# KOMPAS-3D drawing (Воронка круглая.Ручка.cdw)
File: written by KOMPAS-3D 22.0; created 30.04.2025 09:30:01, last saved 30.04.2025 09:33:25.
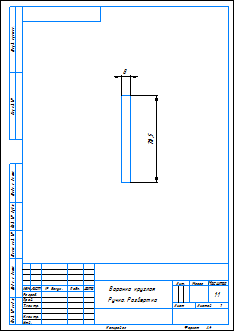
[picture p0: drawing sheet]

Sheet 1: A4, portrait

Document properties: Автор: Admin; Полное имя файла: D:\28.11.2016\3D модели\Абилимпикс\2025\Воронка круглая\Воронка круглая.Ручка..cdw

Title block, sheet 1: Наименование: Воронка круглая / Ручка. Развертка; scale: 1:1; Количество листов документа: 1; Форматы листов документа: A4; stored path: D:\28.11.2016\3D модели\Абилимпикс\2025\Воронка круглая\Воронка круглая Боковина верхняя..cdw

Dimensions and other numbers on the sheet: 8; 78,5; 1:1; 1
